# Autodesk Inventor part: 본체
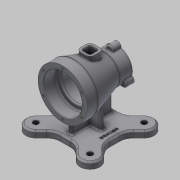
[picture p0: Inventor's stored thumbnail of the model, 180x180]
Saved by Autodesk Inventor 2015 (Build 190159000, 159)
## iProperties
Created: 2018-03
Part Number: 본체
Material: 일반
Document SubType Name: Modeling
Designer: SCD-A011
Density: 1 g/cm^3
Appearance: 기본값
Author: SCD-A011
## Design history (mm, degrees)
sketch "스케치1"
  geometry: L1 (-50, 0)-(50, 0); L2 (-50, 0)-(-50, 45); L3 (-50, 45)-(-30, 45); L4 (-30, 45)-(27, 27.5); L5 (27, 27.5)-(50, 27.5); L6 (50, 27.5)-(50, 0); 2 further points
  constraints: 12 end point, 2 midpoint, 2 perpendicular, 1 coincident, 1 horizontal, 1 parallel, 1 vertical
  dimensions: "d0" = 100 distance of L1.start L1.end; "d1" = 45 distance of L1.start L2.end; "d2" = 20 distance of L2.end L3.end; "d3" = 27.5 distance of L5.end L1.end; "d4" = 77 distance from line of L4.end L2
revolve "회전1" sketch "스케치1" stored, may be unused: angle "d5" = 90 deg
node "작업 평면1"
sketch "스케치2"
  geometry: L1 (45, -45)-(-45, -45); L2 (-45, -45)-(-45, 45); L3 (-45, 45)-(45, 45); L4 (45, 45)-(45, -45); L5 (45, -45)-(-45, 45); L6 (-45, -45)-(45, 45); 1 further point
  constraints: 12 end point, 2 midpoint, 2 parallel, 1 horizontal, 1 perpendicular
  dimensions: "d7" = 90 distance of L2.end L3.end; "d8" = 90 distance of L1.end L2.end
extrude "돌출1" join sketch "스케치2" distance "d9" = 12; taper "d10" = 0 deg
sketch "스케치3" dims "d13" = 140
  geometry: L1 (0, 0)-(-62.225, 62.225); L2 (0, 0)-(0, 13.062); L3 (-12.728, -12.728)-(-62.225, 36.77); L4 (12.728, 12.728)-(-36.77, 62.225); L5 (-12.728, -12.728)-(12.728, 12.728); A1 r 18 centre (-49.497, 49.497) between (-36.77, 62.225) and (-62.225, 36.77); 1 further point
  constraints: 10 end point, 2 parallel, 2 point on circle, 1 centre point, 1 coincident, 1 point on line, 1 vertical, 3 other
  dimensions: "d11" = 88 distance of L1.start L1.end; "d12" = 45 deg angle of L2 L1; "d14" = 36 diameter of A1; "d15" = 18 distance between parallel lines of L1 L3; "d16" = 18 distance between parallel lines of L1 L4
extrude "돌출2" join sketch "스케치3" distance "d17" = 12; taper "d18" = 0 deg
hole "구멍1" diameter "d21" = 10; stored, may be unused: countersink angle "d25" = 90 deg, drill point angle "d27" = 118 deg; dims "d19" = 10, "d20" = 10, "d22" = 6, "d23" = 4, "d24" = 2, "d26" = 8
sketch "스케치4"
  geometry: L1 (-4, -37)-(4, -37); L2 (4, -37)-(4, 37); L3 (4, 37)-(-4, 37); L4 (-4, 37)-(-4, -37); L5 (-4, -37)-(4, 37); L6 (4, -37)-(-4, 37); L7 (24, -4)-(-24, -4); L8 (-24, -4)-(-24, 4); L9 (-24, 4)-(24, 4); L10 (24, 4)-(24, -4); L11 (24, -4)-(-24, 4); L12 (-24, -4)-(24, 4); 1 further point
  constraints: 24 end point, 4 midpoint, 4 parallel, 2 horizontal, 2 perpendicular
  dimensions: "d31" = 8 distance of L2.end L3.end; "d32" = 74 distance of L1.end L2.end; "d33" = 8 distance of L7.end L8.end; "d34" = 48 distance of L8.end L9.end
extrude "돌출3" join sketch "스케치4" stored distance "d35" = 12; taper "d36" = 0 deg
feature "면 기울기1" dims angle "d37" = 5 deg
sketch "스케치5"
  geometry: C1 r 7 at (0, -27.5); 1 further point
  constraints: 2 vertical alignment, 1 centre point, 1 other
  dimensions: "d38" = 14 diameter of C1
extrude "돌출4" join sketch "스케치5" distance "d39" = 15; taper "d40" = 0 deg
node "작업 평면2"
sketch "스케치6"
  geometry: L1 (12.5, -12.5)-(-12.5, -12.5); L2 (-12.5, -12.5)-(-12.5, 12.5); L3 (-12.5, 12.5)-(12.5, 12.5); L4 (12.5, 12.5)-(12.5, -12.5); L5 (12.5, -12.5)-(-12.5, 12.5); L6 (-12.5, -12.5)-(12.5, 12.5); 1 further point
  constraints: 12 end point, 2 midpoint, 2 parallel, 1 horizontal, 1 perpendicular
  dimensions: "d45" = 25 distance of L2.end L3.end; "d46" = 25 distance of L1.end L2.end
extrude "돌출5" join sketch "스케치6" stored distance "d47" = 15; taper "d48" = 0 deg
hole "구멍2" diameter "d51" = 40; stored, may be unused: countersink angle "d55" = 90 deg, drill point angle "d57" = 118 deg; dims "d49" = 10, "d50" = 10, "d52" = 6, "d53" = 70, "d54" = 23, "d56" = 8
hole "구멍3" diameter "d60" = 52; stored, may be unused: countersink angle "d64" = 90 deg, drill point angle "d66" = 0 deg; dims "d58" = 10, "d59" = 10, "d61" = 6, "d62" = 70, "d63" = 23, "d65" = 47
fillet "모깎기1" dims "d67" = 8
sketch "스케치7"
  geometry: L1 (-12.5, -4.5)-(-12.5, 4.5) reference; L2 (4.5, -12.5)-(-4.5, -12.5) reference; L3 (12.5, 4.5)-(12.5, -4.5) reference; L4 (-4.5, 12.5)-(4.5, 12.5) reference; L5 (-4.5, 7.5)-(4.5, 7.5); L6 (7.5, 4.5)-(7.5, -4.5); L7 (4.5, -7.5)-(-4.5, -7.5); L8 (-7.5, -4.5)-(-7.5, 4.5); A1 r 8 centre (-4.5, 4.5) between (-4.5, 12.5) and (-12.5, 4.5) reference; A2 r 8 centre (-4.5, -4.5) between (-12.5, -4.5) and (-4.5, -12.5) reference; A3 r 8 centre (4.5, -4.5) between (4.5, -12.5) and (12.5, -4.5) reference; A4 r 8 centre (4.5, 4.5) between (12.5, 4.5) and (4.5, 12.5) reference; A5 r 3 centre (-4.5, 4.5) between (-4.5, 7.5) and (-7.5, 4.5); A6 r 3 centre (4.5, 4.5) between (7.5, 4.5) and (4.5, 7.5); A7 r 3 centre (4.5, -4.5) between (4.5, -7.5) and (7.5, -4.5); A8 r 3 centre (-4.5, -4.5) between (-7.5, -4.5) and (-4.5, -7.5); 1 further point
  constraints: 8 end point, 8 point on circle, 4 centre point, 7 other
  dimensions: "d68" = 5 radial gap between concentric circles of A1 A5
extrude "돌출6" cut sketch "스케치7" distance "d69" = 30; taper "d70" = 0 deg
sketch "스케치8"
  geometry: C1 r 35 at (0, 0) reference; 1 further point
  constraints: 1 vertical alignment
  dimensions: "d71" = 40 distance of C1.centre point (0, 40)
hole "구멍4" sketch "스케치8" at (0, 40) diameter "d72" = 3.242; stored, may be unused: countersink angle "d76" = 90 deg, drill point angle "d78" = 118 deg; dims "d73" = 9, "d74" = 70, "d75" = 23, "d77" = 11
hole "구멍5" diameter "d84" = 3.242; stored, may be unused: countersink angle "d88" = 90 deg, drill point angle "d90" = 118 deg; dims "d82" = 10, "d83" = 10, "d85" = 9, "d86" = 70, "d87" = 23, "d89" = 11
fillet "모깎기2" dims "d94" = 25
fillet "모깎기3" dims "d95" = 3
fillet "모깎기4" dims "d96" = 3
fillet "모깎기5" dims "d97" = 1
chamfer "모따기1" distance "d98" = 3; stored, may be unused: second distance "d99" = 2, angle "d100" = 45 deg
chamfer "모따기2" distance "d101" = 1; stored, may be unused: second distance "d102" = 2, angle "d103" = 45 deg
fillet "모깎기6" dims "d104" = 3
sketch "스케치9"
  geometry: L1 (9.189, 45)-(-9.189, 45) reference; 2 further points
  constraints: 1 other
  dimensions: "d105" = 35 distance of point (0, 0) point (35, 0); "d106" = 45 distance from line of L1 point (35, 0)
feature "엠보싱1" sketch "스케치9" dims "d11" = 88, "d12" = 45 deg, "d13" = 140, "d14" = 36, "d15" = 18, "d16" = 18, "d107" = 0.5, "d108" = 0
node "솔리드1"
pattern_circular "원형 패턴1" dims angle "d29" = 360 deg
pattern_circular "원형 패턴2" dims angle "d42" = 360 deg
pattern_circular "원형 패턴3" dims angle "d80" = 360 deg
pattern_circular "원형 패턴4" dims angle "d92" = 360 deg
other parameters: "d6" = -82, "d44" = 45
